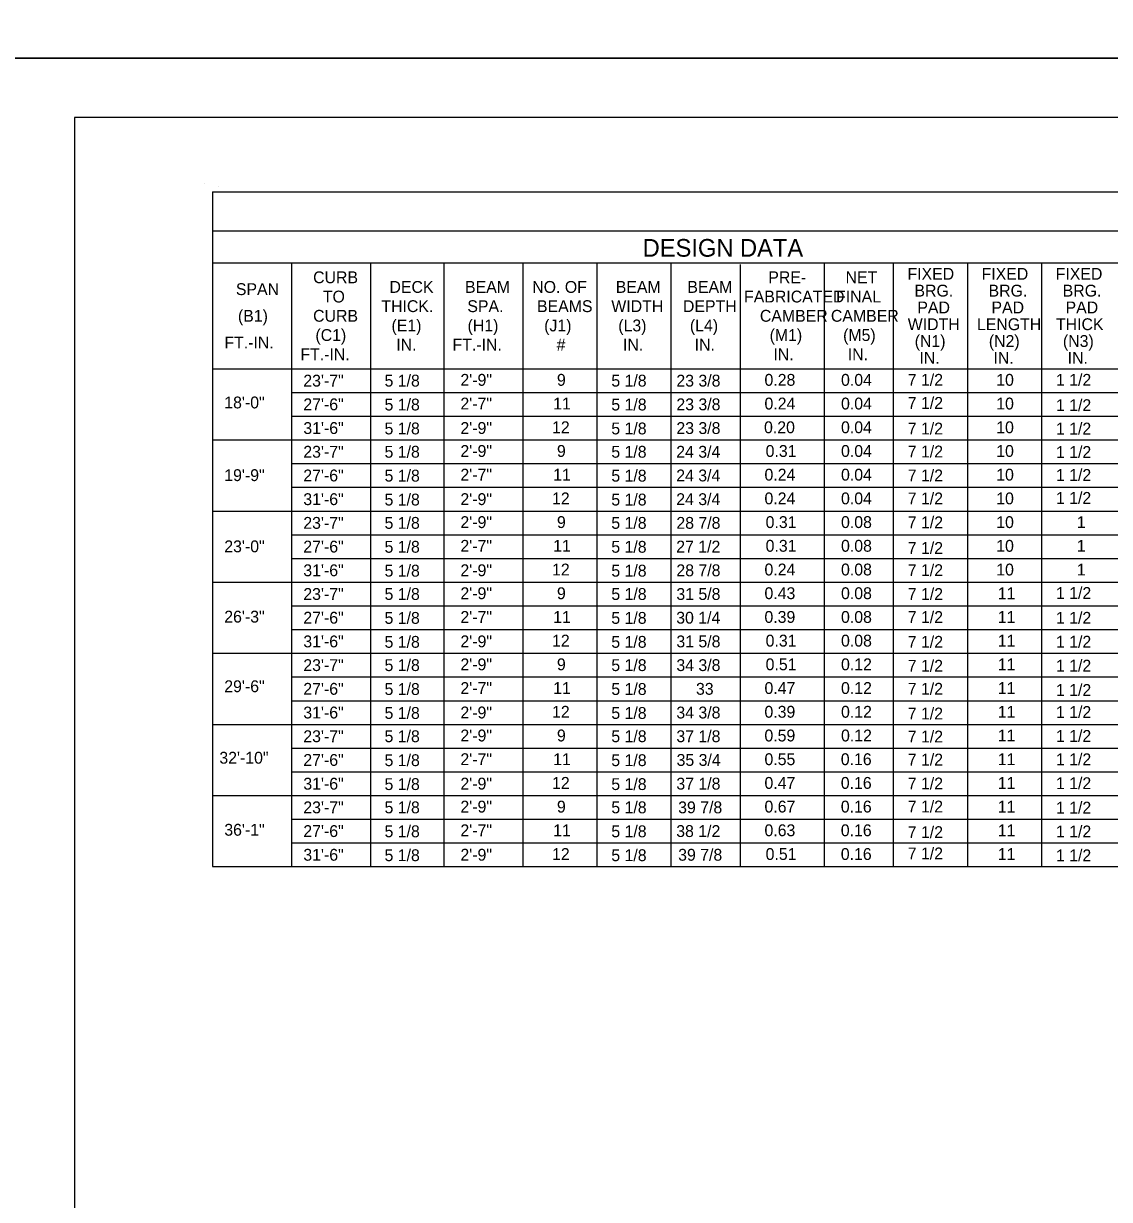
# Model space of a CAD drawing. Extents: x -5022 to -159, y 1126 to 7226.
# Drawn here: x -3813 to -3538.3, y 4400.9 to 4698.6 of the extents above; entities that cross this region are included whole.
import ezdxf

# ---------------------------------------------------------------- set-up
doc = ezdxf.new("R2010")
doc.units = 0
for name, color, linetype in [('2', 7, 'Continuous'), ('3', 7, 'Continuous'), ('PLT-BNDY', 7, 'Continuous')]:
    doc.layers.add(name, color=color, linetype=linetype)

msp = doc.modelspace()

# ---------------------------------------------------------------- linework, layer by layer
at = {"layer": '2'}
for p, q in [((-3014.13, 4674.81), (-3800.13, 4674.81)), ((-3800.13, 4674.81), (-3800.13, 4110.81)), ((-3767.18, 4657.94), (-3767.18, 4657.94)), ((-3763.77, 4657.37), (-3763.77, 4657.37))]:
    msp.add_line(p, q, dxfattribs=at)
at = {"layer": '3'}
for p, q in [((-3765.21, 4655.97), (-3050.36, 4655.98)), ((-3765.21, 4655.97), (-3765.21, 4485.17)), ((-3765.21, 4646.05), (-3050.36, 4646.05)), ((-3765.21, 4637.98), (-3050.36, 4637.99)), ((-3745.21, 4637.98), (-3745.21, 4485.17)), ((-3725.21, 4637.98), (-3725.21, 4485.17)), ((-3706.71, 4637.98), (-3706.71, 4485.17)), ((-3686.71, 4637.98), (-3686.71, 4485.17)), ((-3667.96, 4637.98), (-3667.96, 4485.17)), ((-3649.21, 4637.98), (-3649.21, 4485.17)), ((-3631.71, 4637.59), (-3631.71, 4485.17)), ((-3610.46, 4637.98), (-3610.46, 4485.17)), ((-3592.96, 4637.98), (-3592.96, 4485.17)), ((-3574.21, 4637.98), (-3574.21, 4485.17)), ((-3555.46, 4637.98), (-3555.46, 4485.17)), ((-3765.21, 4611.17), (-3050.36, 4611.18)), ((-3745.21, 4605.17), (-3050.36, 4605.18)), ((-3745.21, 4599.17), (-3050.36, 4599.18)), ((-3765.21, 4593.17), (-3050.36, 4593.18)), ((-3745.21, 4587.17), (-3050.36, 4587.17)), ((-3745.21, 4581.17), (-3050.36, 4581.17)), ((-3765.21, 4575.17), (-3050.36, 4575.17)), ((-3745.21, 4569.17), (-3050.36, 4569.17)), ((-3745.21, 4563.17), (-3050.36, 4563.17)), ((-3765.21, 4557.17), (-3050.36, 4557.18)), ((-3745.21, 4551.17), (-3050.36, 4551.17)), ((-3745.21, 4545.17), (-3050.36, 4545.17)), ((-3765.21, 4539.17), (-3050.36, 4539.17)), ((-3745.21, 4533.17), (-3050.36, 4533.17)), ((-3745.21, 4527.17), (-3050.36, 4527.17)), ((-3765.21, 4521.17), (-3050.36, 4521.17)), ((-3745.21, 4515.17), (-3050.36, 4515.17)), ((-3745.21, 4509.17), (-3050.36, 4509.17)), ((-3765.21, 4503.17), (-3050.36, 4503.17)), ((-3745.21, 4497.17), (-3050.36, 4497.17)), ((-3745.21, 4491.17), (-3050.36, 4491.17)), ((-3765.21, 4485.17), (-3050.36, 4485.17))]:
    msp.add_line(p, q, dxfattribs=at)
at = {"layer": 'PLT-BNDY'}
for points in [[(-3840.13, 5283.81), (-2999.13, 5283.81), (-2999.13, 4689.81), (-3840.13, 4689.81)], [(-3840.13, 4689.81), (-2999.13, 4689.81), (-2999.13, 4095.81), (-3840.13, 4095.81)]]:
    msp.add_lwpolyline(points, close=True, dxfattribs=at)

# ---------------------------------------------------------------- texts
at = {"layer": '2'}
for s, height, p in [('DESIGN DATA', 4.4793, (-3656.36, 4639.54)), ('CURB', 3, (-3739.74, 4632.83)), ('PRE-', 3, (-3624.57, 4632.83)), ('NET', 3, (-3605.03, 4632.83)), ('FIXED', 3, (-3589.36, 4633.7)), ('FIXED', 3, (-3570.61, 4633.7)), ('FIXED', 3, (-3551.86, 4633.7)), ('SPAN', 3, (-3759.28, 4629.83)), ('DECK', 3, (-3720.42, 4630.39)), ('BEAM', 3, (-3701.3, 4630.39)), ('NO. OF', 3, (-3684.3, 4630.39)), ('BEAM', 3, (-3663.17, 4630.39)), ('BEAM', 3, (-3645.05, 4630.39)), ('BRG.', 3, (-3587.59, 4629.45)), ('BRG.', 3, (-3568.84, 4629.45)), ('BRG.', 3, (-3550.09, 4629.45)), ('TO', 3, (-3737.28, 4627.95)), ('THICK.', 3, (-3722.47, 4625.52)), ('SPA.', 3, (-3700.72, 4625.52)), ('BEAMS', 3, (-3683.1, 4625.52)), ('WIDTH', 3, (-3664.29, 4625.52)), ('DEPTH', 3, (-3646.17, 4625.52)), ('FABRICATED', 3, (-3630.71, 4627.95)), ('FINAL', 3, (-3607.42, 4627.95)), ('PAD', 3, (-3586.86, 4625.2)), ('PAD', 3, (-3568.11, 4625.2)), ('PAD', 3, (-3549.36, 4625.2)), ('(B1)', 3, (-3758.76, 4623.08)), ('CURB', 3, (-3739.74, 4623.08)), ('CAMBER', 3, (-3626.7, 4623.08)), ('CAMBER', 3, (-3608.73, 4623.08)), ('(E1)', 3, (-3719.91, 4620.64)), ('(H1)', 3, (-3700.66, 4620.64)), ('(J1)', 3, (-3681.28, 4620.64)), ('(L3)', 3, (-3662.53, 4620.64)), ('(L4)', 3, (-3644.41, 4620.64)), ('WIDTH', 3, (-3589.29, 4620.95)), ('LENGTH', 3, (-3571.79, 4620.95)), ('THICK', 3, (-3551.79, 4620.95)), ('FT.-IN.', 3, (-3762.19, 4616.33)), ('(C1)', 3, (-3739.16, 4618.21)), ('(M1)', 3, (-3624.24, 4618.21)), ('(M5)', 3, (-3605.65, 4618.21)), ('(N1)', 3, (-3587.53, 4616.7)), ('(N2)', 3, (-3568.78, 4616.7)), ('(N3)', 3, (-3550.03, 4616.7)), ('FT.-IN.', 3, (-3742.96, 4613.33)), ('IN.', 3, (-3718.71, 4615.77)), ('FT.-IN.', 3, (-3704.47, 4615.77)), ('#', 3, (-3678.12, 4615.77)), ('IN.', 3, (-3661.34, 4615.77)), ('IN.', 3, (-3643.21, 4615.77)), ('IN.', 3, (-3623.29, 4613.33)), ('IN.', 3, (-3604.46, 4613.33)), ('IN.', 3, (-3586.34, 4612.45)), ('IN.', 3, (-3567.59, 4612.45)), ('IN.', 3, (-3548.83, 4612.45)), ('23\'-7"', 3, (-3742.22, 4606.67)), ('5 1/8', 3, (-3721.67, 4606.67)), ('2\'-9"', 3, (-3702.47, 4606.87)), ('9', 3, (-3678.05, 4606.87)), ('5 1/8', 3, (-3664.29, 4606.67)), ('23 3/8', 3, (-3647.83, 4606.67)), ('0.28', 3, (-3625.54, 4606.87)), ('0.04', 3, (-3606.17, 4606.87)), ('7 1/2', 3, (-3589.29, 4606.87)), ('10', 3, (-3566.9, 4606.87)), ('1 1/2', 3, (-3551.79, 4606.87)), ('18\'-0"', 3, (-3762.22, 4601.15)), ('27\'-6"', 3, (-3742.22, 4600.67)), ('5 1/8', 3, (-3721.67, 4600.62)), ('2\'-7"', 3, (-3702.47, 4600.87)), ('11', 3, (-3679.01, 4600.87)), ('5 1/8', 3, (-3664.29, 4600.62)), ('23 3/8', 3, (-3647.83, 4600.67)), ('0.24', 3, (-3625.54, 4600.87)), ('0.04', 3, (-3606.17, 4600.87)), ('7 1/2', 3, (-3589.29, 4601.03)), ('10', 3, (-3566.9, 4600.87)), ('1 1/2', 3, (-3551.79, 4600.46)), ('31\'-6"', 3, (-3742.22, 4594.67)), ('5 1/8', 3, (-3721.67, 4594.57)), ('2\'-9"', 3, (-3702.47, 4594.68)), ('12', 3, (-3679.29, 4594.87)), ('5 1/8', 3, (-3664.29, 4594.57)), ('23 3/8', 3, (-3647.83, 4594.67)), ('0.20', 3, (-3625.65, 4594.87)), ('0.04', 3, (-3606.17, 4594.87)), ('7 1/2', 3, (-3589.29, 4594.55)), ('10', 3, (-3566.9, 4594.87)), ('1 1/2', 3, (-3551.79, 4594.54)), ('23\'-7"', 3, (-3742.22, 4588.67)), ('5 1/8', 3, (-3721.67, 4588.67)), ('2\'-9"', 3, (-3702.47, 4588.86)), ('9', 3, (-3678.05, 4588.87)), ('5 1/8', 3, (-3664.29, 4588.67)), ('24 3/4', 3, (-3647.87, 4588.67)), ('0.31', 3, (-3625.25, 4588.87)), ('0.04', 3, (-3606.17, 4588.87)), ('7 1/2', 3, (-3589.29, 4588.73)), ('10', 3, (-3566.9, 4588.87)), ('1 1/2', 3, (-3551.79, 4588.61)), ('19\'-9"', 3, (-3762.22, 4582.75)), ('27\'-6"', 3, (-3742.22, 4582.67)), ('5 1/8', 3, (-3721.67, 4582.62)), ('2\'-7"', 3, (-3702.47, 4582.87)), ('11', 3, (-3679.01, 4582.87)), ('5 1/8', 3, (-3664.29, 4582.62)), ('24 3/4', 3, (-3647.87, 4582.67)), ('0.24', 3, (-3625.54, 4582.87)), ('0.04', 3, (-3606.17, 4582.87)), ('7 1/2', 3, (-3589.29, 4582.68)), ('10', 3, (-3566.9, 4582.87)), ('1 1/2', 3, (-3551.79, 4582.8)), ('31\'-6"', 3, (-3742.22, 4576.67)), ('5 1/8', 3, (-3721.67, 4576.57)), ('2\'-9"', 3, (-3702.47, 4576.68)), ('12', 3, (-3679.29, 4576.87)), ('5 1/8', 3, (-3664.29, 4576.57)), ('24 3/4', 3, (-3647.87, 4576.67)), ('0.24', 3, (-3625.54, 4576.87)), ('0.04', 3, (-3606.17, 4576.87)), ('7 1/2', 3, (-3589.29, 4576.85)), ('10', 3, (-3566.9, 4576.87)), ('1 1/2', 3, (-3551.79, 4576.99)), ('23\'-7"', 3, (-3742.22, 4570.67)), ('5 1/8', 3, (-3721.67, 4570.67)), ('2\'-9"', 3, (-3702.47, 4570.86)), ('9', 3, (-3678.05, 4570.87)), ('5 1/8', 3, (-3664.29, 4570.67)), ('28 7/8', 3, (-3647.83, 4570.67)), ('0.31', 3, (-3625.25, 4570.87)), ('0.08', 3, (-3606.17, 4570.87)), ('7 1/2', 3, (-3589.29, 4570.8)), ('10', 3, (-3566.9, 4570.86)), ('1', 3, (-3546.51, 4570.86)), ('23\'-0"', 3, (-3762.22, 4564.73)), ('27\'-6"', 3, (-3742.22, 4564.67)), ('5 1/8', 3, (-3721.67, 4564.62)), ('2\'-7"', 3, (-3702.47, 4564.86)), ('11', 3, (-3679.01, 4564.87)), ('5 1/8', 3, (-3664.29, 4564.62)), ('27 1/2', 3, (-3647.87, 4564.67)), ('0.31', 3, (-3625.25, 4564.87)), ('0.08', 3, (-3606.17, 4564.87)), ('7 1/2', 3, (-3589.29, 4564.32)), ('10', 3, (-3566.9, 4564.86)), ('1', 3, (-3546.51, 4564.86)), ('31\'-6"', 3, (-3742.22, 4558.67)), ('5 1/8', 3, (-3721.67, 4558.57)), ('2\'-9"', 3, (-3702.47, 4558.68)), ('12', 3, (-3679.29, 4558.86)), ('5 1/8', 3, (-3664.29, 4558.57)), ('28 7/8', 3, (-3647.83, 4558.67)), ('0.24', 3, (-3625.54, 4558.87)), ('0.08', 3, (-3606.17, 4558.87)), ('7 1/2', 3, (-3589.29, 4558.7)), ('10', 3, (-3566.9, 4558.86)), ('1', 3, (-3546.51, 4558.86)), ('23\'-7"', 3, (-3742.22, 4552.67)), ('5 1/8', 3, (-3721.67, 4552.67)), ('2\'-9"', 3, (-3702.47, 4552.86)), ('9', 3, (-3678.05, 4552.86)), ('5 1/8', 3, (-3664.29, 4552.67)), ('31 5/8', 3, (-3647.83, 4552.67)), ('0.43', 3, (-3625.54, 4552.87)), ('0.08', 3, (-3606.17, 4552.87)), ('7 1/2', 3, (-3589.29, 4552.66)), ('11', 3, (-3566.51, 4552.86)), ('1 1/2', 3, (-3551.79, 4552.92)), ('26\'-3"', 3, (-3762.22, 4546.94)), ('27\'-6"', 3, (-3742.22, 4546.67)), ('5 1/8', 3, (-3721.67, 4546.62)), ('2\'-7"', 3, (-3702.47, 4546.86)), ('11', 3, (-3679.01, 4546.86)), ('5 1/8', 3, (-3664.29, 4546.62)), ('30 1/4', 3, (-3647.87, 4546.67)), ('0.39', 3, (-3625.55, 4546.86)), ('0.08', 3, (-3606.17, 4546.86)), ('7 1/2', 3, (-3589.29, 4546.83)), ('11', 3, (-3566.51, 4546.86)), ('1 1/2', 3, (-3551.79, 4546.64)), ('31\'-6"', 3, (-3742.22, 4540.67)), ('5 1/8', 3, (-3721.67, 4540.56)), ('2\'-9"', 3, (-3702.47, 4540.68)), ('12', 3, (-3679.29, 4540.87)), ('5 1/8', 3, (-3664.29, 4540.56)), ('31 5/8', 3, (-3647.83, 4540.67)), ('0.31', 3, (-3625.25, 4540.87)), ('0.08', 3, (-3606.17, 4540.87)), ('7 1/2', 3, (-3589.29, 4540.56)), ('11', 3, (-3566.51, 4540.87)), ('1 1/2', 3, (-3551.79, 4540.59)), ('23\'-7"', 3, (-3742.22, 4534.67)), ('5 1/8', 3, (-3721.67, 4534.67)), ('2\'-9"', 3, (-3702.47, 4534.86)), ('9', 3, (-3678.05, 4534.87)), ('5 1/8', 3, (-3664.29, 4534.67)), ('34 3/8', 3, (-3647.83, 4534.67)), ('0.51', 3, (-3625.25, 4534.87)), ('0.12', 3, (-3606.17, 4534.87)), ('7 1/2', 3, (-3589.29, 4534.51)), ('11', 3, (-3566.51, 4534.87)), ('1 1/2', 3, (-3551.79, 4534.54)), ('29\'-6"', 3, (-3762.22, 4529.32)), ('27\'-6"', 3, (-3742.22, 4528.67)), ('5 1/8', 3, (-3721.67, 4528.62)), ('2\'-7"', 3, (-3702.47, 4528.86)), ('11', 3, (-3679.01, 4528.87)), ('5 1/8', 3, (-3664.29, 4528.62)), ('33', 3, (-3642.87, 4528.67)), ('0.47', 3, (-3625.54, 4528.87)), ('0.12', 3, (-3606.17, 4528.87)), ('7 1/2', 3, (-3589.29, 4528.68)), ('11', 3, (-3566.51, 4528.87)), ('1 1/2', 3, (-3551.79, 4528.38)), ('31\'-6"', 3, (-3742.22, 4522.67)), ('5 1/8', 3, (-3721.67, 4522.56)), ('2\'-9"', 3, (-3702.47, 4522.68)), ('12', 3, (-3679.29, 4522.86)), ('5 1/8', 3, (-3664.29, 4522.56)), ('34 3/8', 3, (-3647.83, 4522.67)), ('0.39', 3, (-3625.55, 4522.86)), ('0.12', 3, (-3606.17, 4522.86)), ('7 1/2', 3, (-3589.29, 4522.42)), ('11', 3, (-3566.51, 4522.86)), ('1 1/2', 3, (-3551.79, 4522.8)), ('23\'-7"', 3, (-3742.22, 4516.67)), ('5 1/8', 3, (-3721.67, 4516.67)), ('2\'-9"', 3, (-3702.47, 4516.86)), ('9', 3, (-3678.05, 4516.86)), ('5 1/8', 3, (-3664.29, 4516.67)), ('37 1/8', 3, (-3647.83, 4516.67)), ('0.59', 3, (-3625.55, 4516.86)), ('0.12', 3, (-3606.17, 4516.86)), ('7 1/2', 3, (-3589.29, 4516.59)), ('11', 3, (-3566.51, 4516.86)), ('1 1/2', 3, (-3551.79, 4516.75)), ('32\'-10"', 3, (-3763.47, 4511.23)), ('27\'-6"', 3, (-3742.22, 4510.67)), ('5 1/8', 3, (-3721.67, 4510.61)), ('2\'-7"', 3, (-3702.47, 4510.86)), ('11', 3, (-3679.01, 4510.86)), ('5 1/8', 3, (-3664.29, 4510.61)), ('35 3/4', 3, (-3647.78, 4510.67)), ('0.55', 3, (-3625.54, 4510.86)), ('0.16', 3, (-3606.23, 4510.86)), ('7 1/2', 3, (-3589.29, 4510.76)), ('11', 3, (-3566.51, 4510.86)), ('1 1/2', 3, (-3551.79, 4510.83)), ('31\'-6"', 3, (-3742.22, 4504.66)), ('5 1/8', 3, (-3721.67, 4504.56)), ('2\'-9"', 3, (-3702.47, 4504.68)), ('12', 3, (-3679.29, 4504.86)), ('5 1/8', 3, (-3664.29, 4504.56)), ('37 1/8', 3, (-3647.83, 4504.67)), ('0.47', 3, (-3625.54, 4504.86)), ('0.16', 3, (-3606.23, 4504.86)), ('7 1/2', 3, (-3589.29, 4504.71)), ('11', 3, (-3566.51, 4504.86)), ('1 1/2', 3, (-3551.79, 4504.78)), ('23\'-7"', 3, (-3742.22, 4498.67)), ('5 1/8', 3, (-3721.67, 4498.67)), ('2\'-9"', 3, (-3702.47, 4498.86)), ('9', 3, (-3678.05, 4498.86)), ('5 1/8', 3, (-3664.29, 4498.67)), ('39 7/8', 3, (-3647.38, 4498.67)), ('0.67', 3, (-3625.54, 4498.87)), ('0.16', 3, (-3606.23, 4498.87)), ('7 1/2', 3, (-3589.29, 4498.88)), ('11', 3, (-3566.51, 4498.86)), ('1 1/2', 3, (-3551.79, 4498.61)), ('36\'-1"', 3, (-3762.22, 4493)), ('27\'-6"', 3, (-3742.22, 4492.67)), ('5 1/8', 3, (-3721.67, 4492.61)), ('2\'-7"', 3, (-3702.47, 4492.86)), ('11', 3, (-3679.01, 4492.86)), ('5 1/8', 3, (-3664.29, 4492.61)), ('38 1/2', 3, (-3647.87, 4492.67)), ('0.63', 3, (-3625.54, 4492.87)), ('0.16', 3, (-3606.23, 4492.87)), ('7 1/2', 3, (-3589.29, 4492.4)), ('11', 3, (-3566.51, 4492.86)), ('1 1/2', 3, (-3551.79, 4492.57)), ('31\'-6"', 3, (-3742.22, 4486.67)), ('5 1/8', 3, (-3721.67, 4486.56)), ('2\'-9"', 3, (-3702.47, 4486.68)), ('12', 3, (-3679.29, 4486.86)), ('5 1/8', 3, (-3664.29, 4486.56)), ('39 7/8', 3, (-3647.38, 4486.67)), ('0.51', 3, (-3625.25, 4486.86)), ('0.16', 3, (-3606.23, 4486.86)), ('7 1/2', 3, (-3589.29, 4487.01)), ('11', 3, (-3566.51, 4486.86)), ('1 1/2', 3, (-3551.79, 4486.52))]:
    msp.add_text(s, height=height, dxfattribs=at).set_placement(p)

doc.saveas('drawing.dxf')
